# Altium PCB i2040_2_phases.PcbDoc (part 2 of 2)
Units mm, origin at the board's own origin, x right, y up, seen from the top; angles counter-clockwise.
Board outline 90 x 90 mm, 2 copper layers (Top Layer, Bottom Layer), stack 1.575 mm thick; 116 components, 66 nets, 276 pads, 142 vias.
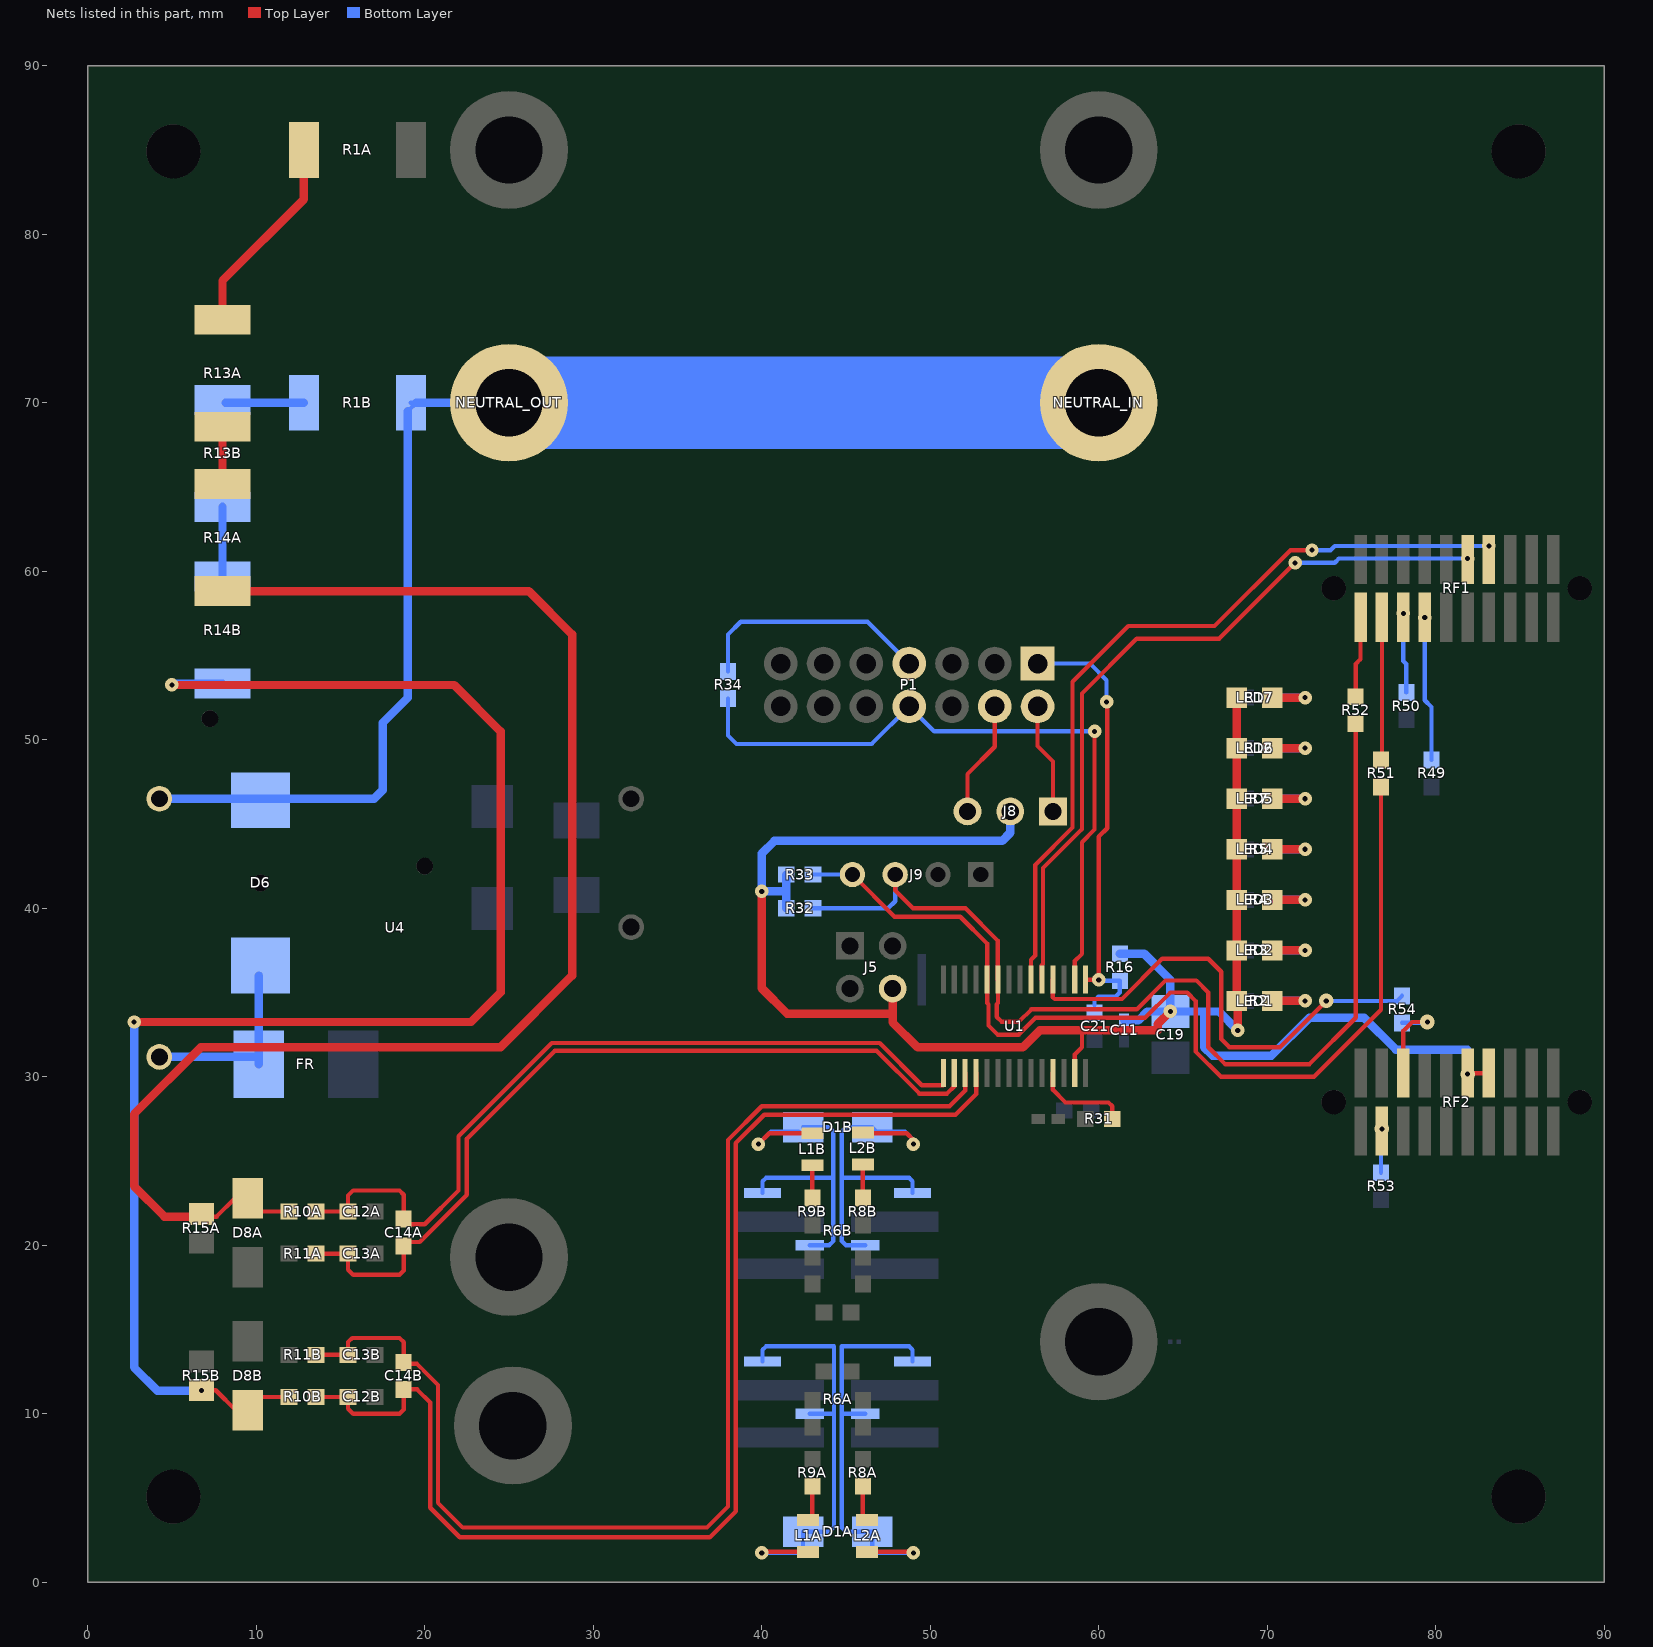
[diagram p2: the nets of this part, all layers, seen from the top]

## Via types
v1: diameter 0.8, hole 0.3, Top Layer to Bottom Layer, 134 vias
v2: diameter 0.864, hole 0.3, Top Layer to Bottom Layer, 6 vias
v3: diameter 0.8, hole 0.3, Top Layer to Bottom Layer, tented top, 2 vias

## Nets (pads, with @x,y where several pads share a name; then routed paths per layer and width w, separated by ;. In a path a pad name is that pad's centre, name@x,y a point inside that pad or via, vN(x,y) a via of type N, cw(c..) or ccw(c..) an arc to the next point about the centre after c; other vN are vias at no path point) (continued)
NetD1A_1: D1A.1 L2A.1 R6A.3 R6A.5 | length 25
  Top Layer w0.254: L2A.1@46.5,1.804 v1@48.946,1.804
  Bottom Layer w0.254: 44.75,10 R6A.3@46.15,10 ; R6A.5@48.95,13.1 48.95,13.8 48.75,14 44.75,14 44.75,3.25 45,3 D1A.1@46.55,3 46.55,2.004 46.804,1.75 v1(49,1.75)
NetD1A_2: D1A.2 L1A.1 R6A.4 R6A.6 | length 25.1
  Top Layer w0.254: v1@40.054,1.804 L1A.1@42.5,1.804
  Bottom Layer w0.254: v1(40,1.75) 42.25,1.75 42.45,1.95 D1A.2@42.45,3 44,3 44.293,3.293 44.293,14 40.25,14 40.05,13.8 R6A.6@40.05,13.1 ; R6A.4@42.85,10 44.25,10
NetD1B_1: D1B.1 L2B.1 R6B.3 R6B.5 | length 20.8
  Top Layer w0.254: L2B.1@46.5,26.646 48.604,26.646 49,26.25 v1(49,26)
  Bottom Layer w0.254: R6B.3@46.15,20 45,20 44.75,20.25 44.75,24 ; R6B.5@48.95,23.1 48.95,23.8 48.75,24 44.75,24 ; v1(49,26) 49,26.25 48.5,26.75 46.8,26.75 D1B.1@46.55,27 45,27 44.75,26.75 44.75,24
NetD1B_2: D1B.2 L1B.1 R6B.4 R6B.6 | length 20.6
  Top Layer w0.254: v1(39.8,26) 40.446,26.646 L1B.1@42.5,26.646
  Bottom Layer w0.254: v1(39.8,26) 40.55,26.75 D1B.2@42.2,26.75 ; R6B.6@40.05,23.1 40.05,23.8 40.25,24 44.25,24 ; D1B.2@42.45,27 44,27 44.25,26.75 44.25,24 ; R6B.4@42.85,20 44,20 44.25,20.25 44.25,24
NetD6_1: D6.1 FR.1 U4.2 | length 11.1
  Bottom Layer w0.254: D6.1@10.15,36 D6.1@10.25,36.1
  Bottom Layer w0.5: U4.2@4.25,31.176 FR.1@10,31.176 ; FR.1@10.15,30.75 D6.1@10.15,36
NetD8A_2: D8A.2 R10A.1 R14A.2 R15A.2 | length 86.9
  Top Layer w0.254: R15A.2@6.5,21.7 7.65,21.7 8.75,22.8 D8A.2@9.5,22.8 ; D8A.2@8.8,22.05 9.5,22.05 9.55,22 R10A.1@11.95,22
  Top Layer w0.5: R15A.2@6.5,21.7 4.55,21.7 2.75,23.5 2.75,27.786 6.714,31.75 24.5,31.75 28.75,36 28.75,56.25 26.175,58.825 R14A.2@8,58.825
NetD8B_2: D8B.2 R10B.1 R14B.2 R15B.2 | length 92.4
  Top Layer w0.254: R15B.2@6.75,11.4 7.6,11.4 8.8,10.2 D8B.2@9.5,10.2 ; D8B.2@9.5,11 R10B.1@11.95,11
  Top Layer w0.5: v1(2.75,33.25) 22.75,33.25 24.5,35 24.5,50.5 21.75,53.25 v1(5,53.25)
  Bottom Layer w0.254: v1(5,53.25) v1@5.075,53.325
  Bottom Layer w0.5: v1(2.75,33.25) 2.75,12.75 4.125,11.375 v1(6.75,11.375) ; v1@5.075,53.325 R14B.2@8,53.325
NetJ8_1: J8.1 P1.2 | length 6.6
  Top Layer w0.254: P1.2@56.37,51.98 56.37,49.63 57.29,48.71 J8.1@57.29,45.75
NetJ8_3: J8.3 P1.4 | length 6.9
  Top Layer w0.254: J8.3@52.21,45.75 52.21,47.96 53.83,49.58 P1.4@53.83,51.98
NetL1A_2: L1A.2 R9A.1 | length 2
  Top Layer w0.254: L1A.2@43,3.704 R9A.1@43,5.7
NetL1B_2: L1B.2 R9B.1 | length 1.9
  Top Layer w0.254: R9B.1@43,22.8 L1B.2@43,24.746
NetL2A_2: L2A.2 R8A.1 | length 2
  Top Layer w0.254: L2A.2@46,3.704 R8A.1@46,5.7
NetL2B_2: L2B.2 R8B.1 | length 1.9
  Top Layer w0.254: R8B.1@46,22.8 L2B.2@46,24.746
NetLED1_2: LED1.2 R2.2 | length 3.9
  Top Layer w0.5: LED1.2@70.3,34.5 v1(72.25,34.5)
  Bottom Layer w0.5: R2.2@70.3,34.5 v1(72.25,34.5)
NetLED2_2: LED2.2 R3.2 | length 3.9
  Top Layer w0.5: LED2.2@70.3,37.5 v1(72.25,37.5)
  Bottom Layer w0.5: R3.2@70.3,37.5 v1(72.25,37.5)
NetLED3_2: LED3.2 R4.2 | length 3.9
  Top Layer w0.5: LED3.2@70.3,40.5 v1(72.25,40.5)
  Bottom Layer w0.5: R4.2@70.3,40.5 v1(72.25,40.5)
NetLED4_2: LED4.2 R5.2 | length 3.9
  Top Layer w0.5: LED4.2@70.3,43.5 v1(72.25,43.5)
  Bottom Layer w0.5: R5.2@70.3,43.5 v1(72.25,43.5)
NetLED5_2: LED5.2 R7.2 | length 3.9
  Top Layer w0.5: LED5.2@70.3,46.5 v1(72.25,46.5)
  Bottom Layer w0.5: R7.2@70.3,46.5 v1(72.25,46.5)
NetLED6_2: LED6.2 R12.2 | length 3.9
  Top Layer w0.5: LED6.2@70.3,49.5 v1(72.25,49.5)
  Bottom Layer w0.5: R12.2@70.3,49.5 v1(72.25,49.5)
NetLED7_2: LED7.2 R17.2 | length 3.9
  Top Layer w0.5: LED7.2@70.3,52.5 v1(72.25,52.5)
  Bottom Layer w0.5: R17.2@70.3,52.5 v1(72.25,52.5)
NetP1_7: P1.7 R34.2 | length 14.3
  Bottom Layer w0.254: R34.2@38,54.05 38,56.25 38.75,57 46.27,57 P1.7@48.75,54.52
NetR1A_2: R1A.2 R13A.1 | length 12.1
  Top Layer w0.5: R13A.1@8,74.925 8,77.25 12.825,82.075 R1A.2@12.825,85
NetR1B_2: R1B.2 R13B.1 | length 4.6
  Bottom Layer w0.5: R13B.1@8.175,70 R1B.2@12.825,70
NetR13A_2: R13A.2 R14A.1 | length 3.4
  Top Layer w0.5: R14A.1@8,65.175 R13A.2@8,68.575
NetR13B_2: R13B.2 R14B.1 | length 4.2
  Bottom Layer w0.5: R14B.1@8,59.675 R13B.2@8,63.825
NetR31_2: R31.2 U1.11 | length 5.7
  Top Layer w0.254: U1.11@57.275,30.225 57.275,29.225 58.025,28.475 60.581,28.475 60.8,28.256 R31.2@60.8,27.5
NetR49_1: R49.1 RF1.14 | length 8.6
  Bottom Layer w0.254: v1(79.345,57.25) 79.345,52.345 79.75,51.94 R49.1@79.75,48.8
NetR50_1: R50.1 RF1.16 | length 4.8
  Bottom Layer w0.254: v1(78.075,57.5) 78.075,54.675 78.25,54.5 R50.1@78.25,52.8
NetR51_1: R51.1 RF1.18 | length 8.4
  Top Layer w0.254: R51.1@76.805,48.855 RF1.18@76.805,57.265
NetR52_1: R52.1 RF1.20 | length 4.6
  Top Layer w0.254: R52.1@75.25,52.8 75.25,54.5 75.535,54.785 RF1.20@75.535,57.265
NetR53_1: R53.1 RF2.18 | length 2.6
  Bottom Layer w0.254: R53.1@76.75,24.3 76.75,26.847 v2(76.805,26.902)
NetR54_2: R54.2 RF2.15 | length 5.7
  Top Layer w0.254: RF2.15@78.075,30.215 78.075,32.725 78.6,33.25 v2(79.5,33.25)
  Bottom Layer w0.254: R54.2@78,33.2 79.45,33.2 v2(79.5,33.25)
NEUTRAL: D6.2 NEUTRAL_IN.1 NEUTRAL_OUT.1 R1B.1 U4.1 | length 83.6
  Bottom Layer w0.254: R1B.1@19,69.5 R1B.1@19.5,70 ; R1B.1@19.175,70 NEUTRAL_OUT.1@25,70
  Bottom Layer w0.5: U4.1@4.25,46.5 17,46.5 17.5,47 17.5,51 19,52.5 R1B.1@19,69.5 ; R1B.1@19.5,70 NEUTRAL_OUT.1@25,70
  Bottom Layer w5.5: NEUTRAL_OUT.1@25,70 NEUTRAL_IN.1@60,70
P1.1: R54.1 U1.18 | length 28.8
  Top Layer w0.254: U1.18@57.275,35.775 57.275,34.725 57.38,34.62 61.38,34.62 63.76,37 66.5,37 67.265,36.235 67.265,32.235 67.75,31.75 70.75,31.75 v2(73.5,34.5)
  Bottom Layer w0.254: v2@73.283,34.5 77.7,34.5 R54.1@78,34.8
RXD: RF1.9 U1.19 | length 44.2
  Top Layer w0.254: U1.19@56.625,35.775 56.625,36.625 56.687,36.687 56.687,42.384 59,44.696 59,52.75 62.25,56 67.155,56 v1(71.655,60.5)
  Bottom Layer w0.254: v1(71.655,60.5) 74,60.5 74.25,60.75 v1(81.885,60.75)
SBWTCK: P1.8 R34.1 U1.16 | length 40.9
  Top Layer w0.254: U1.16@58.575,35.775 58.575,36.867 59,37.292 59,43.919 59.75,44.669 v1(59.75,50.5)
  Bottom Layer w0.254: R34.1@38,52.45 38,50.25 38.5,49.75 46.52,49.75 P1.8@48.75,51.98 50.23,50.5 v1(59.75,50.5)
SBWTDIO: C21.1 P1.1 R16.2 U1.15 | length 27
  Top Layer w0.254: U1.15@59.225,35.775 59.25,35.75 v1(60,35.75) ; v1@60,35.7 60,44.25 60.5,44.75 v1@60.5,52
  Bottom Layer w0.254: P1.1@56.37,54.52 59.48,54.52 60.465,53.535 v1(60.465,52.25) ; C21.1@59.75,34.25 59.75,34.524 59.976,34.75 61,34.75 61.25,35 R16.2@61.25,35.7 v1@60.05,35.7
SIMO: J9.4 R33.1 R51.2 U1.24 | length 60.1
  Top Layer w0.254: J9.4@45.38,42 47.88,39.5 51.783,39.5 53.375,37.908 U1.24@53.375,35.775 53.375,34.383 53.455,34.302 53.455,33.045 54,32.5 55.25,32.5 56.25,33.5 62.75,33.5 64.25,35 65.25,35 65.749,34.501 65.749,31.501 67.25,30 72.777,30 76.75,33.973 R51.2@76.75,47.125
  Bottom Layer w0.254: R33.1@43.05,42 J9.4@45.38,42
SOMI: J9.3 R32.1 R52.2 U1.23 | length 64.4
  Top Layer w0.254: J9.3@47.92,42 47.92,41.06 48.98,40 52.086,40 54,38.086 U1.23@54,35.775 ; U1.23@54.025,35.775 54.025,34.383 53.945,34.302 53.945,33.555 54.23,33.27 55.27,33.27 56,34 62.25,34 63.957,35.707 65.793,35.707 66.5,35 66.5,31.75 67.5,30.75 72.5,30.75 75.25,33.5 R52.2@75.25,50.95
  Bottom Layer w0.254: R32.1@43.05,40 47.5,40 47.92,40.42 J9.3@47.92,42
TXD: RF1.7 U1.20 | length 46.7
  Top Layer w0.254: U1.20@55.975,35.775 55.975,36.942 56.23,37.198 56.23,42.573 58.445,44.788 58.445,53.445 61.75,56.75 66.872,56.75 71.372,61.25 v1(72.655,61.25)
  Bottom Layer w0.254: v1(72.655,61.25) 73.75,61.25 74,61.5 v1(83.155,61.5)
VCC: C11.1 C19.1 J5.4 J8.2 LED1.1 LED2.1 LED3.1 LED4.1 LED5.1 LED6.1 LED7.1 R16.1 R32.2 R33.2 RF2.7 RF2.9 U1.13 | length 114.4
  Top Layer w0.254: U1.13@58.575,30.225 58.575,31.325 59,31.75 59,32.75 ; LED1.1@68.195,34.495 LED1.1@68.25,34.441 ; RF2.9@81.885,30.215 RF2.7@83.155,30.215
  Top Layer w0.5: v1(40,41) 40,35.25 41.5,33.75 47.77,33.75 ; J5.4@47.77,35.23 47.77,33.75 ; v1(64.25,33.875) 63.5,33.125 63.5,32.75 56.5,32.75 55.5,31.75 49.25,31.75 47.77,33.23 47.77,33.75 ; LED1.1@68.195,34.495 LED2.1@68.195,37.495 LED3.1@68.195,40.495 LED4.1@68.195,43.495 LED5.1@68.195,46.495 LED6.1@68.195,49.495 LED7.1@68.195,52.495 ; v1(68.25,32.75) LED1.1@68.25,34.441
  Bottom Layer w0.5: R32.2@41.45,40 41.45,41 ; R33.2@41.45,42 41.45,41 ; J8.2@54.75,45.75 54.75,44.48 54.27,44 40.75,44 40,43.25 v1(40,41) 41.45,41 ; R16.1@61.25,37.3 62.7,37.3 64.25,35.75 v1(64.25,33.875) ; C11.1@61.5,33.35 62.35,33.35 62.875,33.875 v1(64.25,33.875) ; 66.25,33.875 66.25,31.75 66.75,31.25 70.25,31.25 72.5,33.5 75.75,33.5 77.635,31.615 81.885,31.615 v2(81.885,30.152) ; v1(68.25,32.75) 67.125,33.875 v1(64.25,33.875)
VIN_MA: C13A.2 C14A.2 R11A.2 U1.2 | length 48.8
  Top Layer w0.254: R11A.2@13.55,19.5 C13A.2@15.45,19.5 15.45,18.55 15.75,18.25 18.5,18.25 18.75,18.5 C14A.2@18.75,19.525 ; C14A.2@18.75,20.2 19.7,20.2 22.5,23 22.5,26.321 27.722,31.543 46.811,31.543 49.353,29 51,29 51.425,29.425 U1.2@51.425,30.225
VIN_MB: C12B.1 C14B.1 R10B.2 U1.4 | length 73.5
  Top Layer w0.254: R10B.2@13.55,11 C12B.1@15.45,11 15.45,10.3 15.75,10 18.5,10 18.75,10.25 C14B.1@18.75,11.45 19.55,11.45 20.33,10.67 20.33,4.42 22.08,2.67 36.92,2.67 38.457,4.207 38.457,26.061 40.147,27.75 51.5,27.75 52.725,28.975 U1.4@52.725,30.225
VIN_PA: C12A.1 C14A.1 R10A.2 U1.1 | length 48
  Top Layer w0.254: R10A.2@13.55,22 C12A.1@15.45,22 15.45,22.95 15.75,23.25 18.5,23.25 18.75,23 C14A.1@18.75,21.55 19.05,21.25 20,21.25 22,23.25 22,26.467 27.533,32 47,32 49.5,29.5 U1.1@50.775,29.5 ; U1.1@50.775,29.552 U1.1@50.775,30.225
VIN_PB: C13B.2 C14B.2 R11B.2 U1.3 | length 73.3
  Top Layer w0.254: R11B.2@13.55,13.5 C13B.2@15.45,13.5 15.45,14.254 15.696,14.5 18.5,14.5 18.75,14.25 C14B.2@18.75,13.05 ; C14B.2@18.75,12.963 19.537,12.963 20.787,11.713 20.787,4.713 22.25,3.25 36.75,3.25 38,4.5 38,26.25 40,28.25 51.137,28.25 52.075,29.188 U1.3@52.075,30.225
pads on no net: H1.1 H2.1 H3.1 H4.1 Logo1.0 P1.3 P1.5 P1.6 P1.10 P1.11 P1.12 P1.13 P1.14 RF1. RF1.2 RF1.4 RF1.5 RF1.6 RF1.8 RF1.10 RF1.11 RF1.12 RF1.13 RF1.15 RF1.17 RF2. RF2.1 RF2.3 RF2.4 RF2.5 RF2.6 RF2.8 RF2.10 RF2.11 RF2.12 RF2.13 RF2.14 RF2.16 RF2.17 RF2.19

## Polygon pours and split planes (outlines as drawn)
AGND on Bottom Layer "Bottom Layer-No Net" (solid, remove dead copper, pour order 4): 1,32.5 65.75,32.5 65.75,1 1,1 1,35.75
DGND on Bottom Layer "Bottom Layer-No Net 1" (solid, pour order 7): 72.5,55 72.5,65 89,65 89,1 66.25,1 66.25,55 72.5,55
DGND on Bottom Layer "Bottom Layer-No Net 2" (solid, pour order 13): 35,57.5 65,57.5 65,34.35 64.9,34.25 35,34.25
AGND on Top Layer "Top Layer-No Net" (solid, remove dead copper, pour order 6): 1,1 1,33.25 65.75,33.25 65.75,1 1,1
DGND on Top Layer "Top Layer-No Net 1" (solid, pour order 9): 72.5,65 89,65 89,1 66.25,1 66.25,55 72.5,55 72.5,65
DGND on Top Layer "Top Layer-No Net 2" (solid, pour order 11): 35,57.5 65,57.5 65,34.25 35,34.25

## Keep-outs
Keep-Out Layer:
  lines w1.2: -0.6,0 ccw(c0,0) 0,-0.6 90,-0.6 ccw(c90,0) 90.6,0 90.6,90 ccw(c90,90) 90,90.6 0,90.6 ccw(c0,90) -0.6,90 -0.6,0
  text ".Layer_Name" at 14.656,-21.806 h1.52

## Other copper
Top Layer:
  text ".Layer_Name" at 14.656,-21.806 h1.52
Bottom Layer:
  rectangle net LIVE_1B: 35,16.6 38.5,22
  rectangle net LIVE_1_A: 35,6.6 38.5,12
  rectangle net LIVE_1: 50.5,16.6 54,22
  rectangle net LIVE_1: 50.5,6.6 54,12
  text ".Layer_Name" at 14.656,-21.806 h1.52

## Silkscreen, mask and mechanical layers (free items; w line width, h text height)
Top Overlay:
  text "Danger High Voltage" at 28.5,76.75 h1.5
  text "CAUTION" at 13,62 h2
  text "MSP430i2040 2 Phases Embedded Meter EVM" at 36,61.75 h1.8
  text "Debugging Interfaces" at 13,59.75 h2
  text ".PCB_Rev" at 36,59 h1.52
  text "ARE NOT ISOLATED" at 13,57.5 h2
  text "Disconnect Debugger" at 13,55.5 h2
  text "Before Applying Line" at 13,53.25 h2
  text "Voltage to the Board" at 13,51 h2
  text "EXT 2-3" at 50.5,47.5 h0.8
  text "FET 1-2" at 54.75,43.25 h0.8
  text "0V" at 41.75,37.25 h1.02
  text "3.3V" at 40,34.5 h1.02
  text "CAUTION" at 80,34.25 h2 r90
  text "Serial Interfaces" at 82.9,34.2 h2 r90
  text "ARE NOT ISOLATED" at 84.9,34.2 h2 r90
  text "Danger High Voltage" at 56,9 h1.5
  text "Danger High Voltage" at 10.5,2.5 h1.5
  text ".Layer_Name" at 14.656,-21.806 h1.52
Bottom Overlay:
  rectangle: 30.38,92 38,94.54
  text ".PRJ_Number" at 54.916,92.254 h1.52
  text "-" at 39.651,91.987 h1.52
  text "Danger High Voltage" at 55.75,76.75 h1.5
  text "Texas Instruments" at 49.5,61.5 h1.52
  text ".CopyrightYear" at 58.25,61.5 h1.52
  text "©" at 61,61.5 h2.67
  text "Caution Hot Surface" at 54.5,14.25 h1.5
  text "Danger High Voltage" at 83.192,9.148 h1.5
  text "Danger High Voltage" at 37.192,2.398 h1.5
  text "UL94V-0" at 79.75,1.25 h1.52
  text ".Layer_Name" at 14.656,-21.806 h1.52
Top Paste:
  text ".Layer_Name" at 14.656,-21.806 h1.52
Bottom Paste:
  text ".Layer_Name" at 14.656,-21.806 h1.52
Top Solder:
  text ".Layer_Name" at 14.656,-21.806 h1.52
  text ".Layer_Name" at 14.656,-21.806 h1.52
Bottom Solder:
  text ".Layer_Name" at 14.656,-21.806 h1.52
Drill Guide:
  text ".Layer_Name" at 14.656,-21.806 h1.52
M1 Board Outline:
  the board outline again, w0.254
  text ".PRJ_Title" at 81.5,-5 h1.02
M2 Board Dimensions:
  rectangle: 3.162,-10.427 12.687,-7.252
  rectangle: -0.013,-7.252 3.162,-4.077
  lines w0.178: -0.013,-7.252 25.387,-7.252 ; 3.162,-10.427 3.162,-4.077 ; 6.337,-10.427 6.337,-4.077 ; 12.687,-10.427 12.687,-4.077 ; 19.037,-10.427 19.037,-4.077 ; -0.013,-10.427 -0.013,-4.077 25.387,-4.077 25.387,-10.427 -0.013,-10.427
  lines w0.254: -0.013,-12.078 -0.013,-11.57 ; 1.511,-12.332 -0.013,-11.824 ; 1.511,-11.316 -0.013,-11.824 ; 6.187,-11.824 -0.013,-11.824 ; 19.188,-11.824 25.387,-11.824 ; 23.863,-12.332 25.387,-11.824 ; 23.863,-11.316 25.387,-11.824 ; 25.387,-12.078 25.387,-11.57
  text ".PRJ_Title" at 81.5,-5 h1.02
  text "25.4 (mm)" at 6.441,-12.738 h1.52
M3 3D STEP Top:
  text ".Layer_Name" at 14.656,-21.806 h1.52
M4 3D STEP Bottom:
  text ".Layer_Name" at 14.656,-21.806 h1.52
M5 Assembly Top:
  lines w0.254: -7.417,-23.626 160.223,-23.626 ; -7.417,-18.462 160.274,-18.462 ; -7.417,-13.297 -7.417,-28.791 94.31,-28.791 160.274,-28.791 160.274,-13.297 -7.404,-13.297 -7.404,-28.791 32.614,-28.791 ; 55.194,-28.791 55.194,-13.297 ; 87.376,-18.462 87.376,-13.297 ; 108.712,-18.462 108.712,-13.297 ; 124.511,-28.956 124.511,-23.804
  text "COMPONENTS MARKED 'DNP' SHOULD NOT BE POPULATED." at 29.299,-8.09 h1.52
  text "ASSEMBLY VARIANT:" at 29.286,-11.024 h1.52
  text ".VariantName" at 55.601,-11.024 h1.52
  text "PCB VIEWED FROM TOP SIDE" at -5.804,-16.654 h1.52
  text "BOARD #:" at 57.099,-16.654 h1.52
  text ".PRJ_Number" at 70.955,-16.654 h1.52
  text "REV:" at 92.405,-16.654 h1.52
  text ".PCB_Rev" at 99.809,-16.654 h1.52
  text "SVN REV:" at 113.69,-16.654 h1.52
  text ".VersionControl_RevNumber" at 126.543,-16.654 h1.52
  text "IGNORE ->" at -5.804,-21.806 h1.52
  text "PLOT NAME =" at -5.804,-27.034 h1.52
  text ".plot_File_Name" at 14.656,-27.034 h1.52
  text "GENERATED    :" at 57.15,-27.034 h1.52
  text ".Print_Date" at 79.235,-27.034 h1.52
  text ".Print_Time" at 97.752,-27.034 h1.52
  text "TEXAS INSTRUMENTS" at 129.87,-27.034 h1.52
M6 Assembly Bottom:
  lines w0.254: -7.429,-18.474 160.261,-18.474 ; -7.379,-23.639 160.261,-23.639 ; 28.334,-28.969 28.334,-23.817 ; 44.133,-18.474 44.133,-13.31 ; 65.468,-18.474 65.468,-13.31 ; 97.65,-28.804 97.65,-13.31 ; 120.231,-28.804 160.249,-28.804 160.249,-13.31 -7.429,-13.31 -7.429,-28.804 58.534,-28.804 160.261,-28.804 160.261,-13.31
  text "COMPONENTS MARKED 'DNP' SHOULD NOT BE POPULATED." at 154.991,-8.077 h1.52
  text ".VariantName" at 128.473,-11.024 h1.52
  text "ASSEMBLY VARIANT:" at 154.864,-11.024 h1.52
  text ".VersionControl_RevNumber" at 26.302,-16.667 h1.52
  text "SVN REV:" at 39.154,-16.667 h1.52
  text ".PCB_Rev" at 53.035,-16.667 h1.52
  text "REV:" at 60.439,-16.667 h1.52
  text ".PRJ_Number" at 81.89,-16.667 h1.52
  text "BOARD #:" at 95.745,-16.667 h1.52
  text "PCB VIEWED FROM BOTTOM SIDE" at 158.648,-16.667 h1.52
  text "IGNORE ->" at 64.715,-21.806 h1.52
  text "TEXAS INSTRUMENTS" at 22.974,-27.047 h1.52
  text ".Print_Time" at 55.093,-27.047 h1.52
  text ".Print_Date" at 73.609,-27.047 h1.52
  text "GENERATED    :" at 95.694,-27.047 h1.52
  text ".plot_File_Name" at 138.189,-27.047 h1.52
  text "PLOT NAME =" at 158.648,-27.047 h1.52
M9 Title Sheet:
  drawing of 57 lines, arcs and shapes, not listed
  text "1" at 18.792,204.127 h1.78
  text "2" at 82.182,204.127 h1.78
  text "3" at 145.411,204.127 h1.78
  text "4" at 209.08,204.127 h1.78
  text "5" at 272.555,204.127 h1.78
  text "6" at 336.182,204.127 h1.78
  text "A" at -10.579,175.095 h1.78
  text "A" at 365.341,175.095 h1.78
  text "B" at -10.579,114.643 h1.78
  text "B" at 365.341,114.643 h1.78
  text "C" at -10.579,54.318 h1.78
  text "C" at 365.341,54.318 h1.78
  text "PROJECT TITLE:" at 288.125,7.048 h1.14
  text ".PRJ_Title" at 289.395,3.662 h1.78
  text "DESIGNED FOR:" at 288.125,-0.597 h1.14
  text ".PRJ_Customer" at 289.395,-4.153 h1.78
  text "D" at -10.579,-5.88 h1.78
  text "D" at 365.341,-5.88 h1.78
  text "FILE NAME:" at 288.125,-8.217 h1.14
  text ".PCB_File_Name_No_Path" at 289.395,-11.265 h1.78
  text "Texas Instruments (TI) and/or its licensors do not warrant the accuracy or completeness of this specification" at 161.9,-15.376 h1.14
  text "ENGINEER:" at 288.125,-15.583 h1.14
  text "LAYOUT BY:" at 326.352,-15.583 h1.14
  text "or any information contained therein. TI and/or its licensors do not warrant that this design will meet" at 160.757,-18.237 h1.14
  text ".PRJ_Engineer" at 289.395,-19.52 h1.78
  text ".PCB_Layout" at 327.635,-19.52 h1.78
  text "the specifications, will be suitable for your application or fit for any particular purpose, or will operate in" at 160.757,-21.099 h1.14
  text ".Layer_Name" at 14.656,-21.806 h1.52
  text "ALTIUM DESIGNER VERSION:" at 326.352,-23.457 h1.14
  text "an implementation. TI and/or its licensors do not warrant that the design is production worthy. You should" at 160.757,-23.961 h1.14
  text "completely validate and test your design implementation to confirm the system functionality for your application." at 161.9,-26.822 h1.14
  text ".print_Scale" at 289.395,-26.843 h1.78
  text ".Application_BuildNumber" at 327.635,-26.843 h1.78
  text "1" at 18.792,-32.093 h1.78
  text "2" at 82.182,-32.093 h1.78
  text "3" at 145.411,-32.093 h1.78
  text "4" at 209.08,-32.093 h1.78
  text "5" at 272.555,-32.093 h1.78
  text "6" at 336.182,-32.093 h1.78
M10 Fab Notes:
  drawing of 212 lines, arcs and shapes, not listed
  text "DESIGN INFORMATION" at 314.478,172.974 h1.52
  text "(REFER ALSO ARRAY/PANEL PROFILING INFORMATION)" at 305.294,168.866 h1.52
  text "BOARD SIZE" at 287.87,168.758 h1.52
  text "3450MIL" at 299.613,165.511 h1.52
  text "X" at 312.457,165.511 h1.52
  text "4950MIL" at 318.333,165.511 h1.52
  text "Number of Layers :" at 298.106,160.503 h1.52
  text "2" at 325.914,160.249 h1.52
  text "MIN. TRACK WIDTH:" at 298.106,156.972 h1.52
  text "8" at 325.951,156.972 h1.52
  text "MIL" at 329.881,156.972 h1.52
  text "MIN. CLEARANCE:" at 298.106,153.619 h1.52
  text "8" at 325.951,153.619 h1.52
  text "MIL" at 329.881,153.619 h1.52
  text "MIN. VIA PAD SIZE:" at 298.106,150.266 h1.52
  text "24" at 325.189,150.266 h1.52
  text "MIL" at 329.881,150.266 h1.52
  text "0.05mm (2MIL)" at 315.759,146.667 h1.52
  text "MINIMUM ANNULAR RING" at 289.744,146.558 h1.52
  text "EXTERNAL" at 333.742,146.558 h1.52
  text "PER" at 294.824,143.561 h1.52
  text "IPC-D-275 CLASS 2 LEVEL C" at 300.412,143.561 h1.52
  text "MIL, HOLES" at 338.213,140.709 h1.52
  text "+/-" at 328.244,140.691 h1.52
  text "+/-" at 349.936,140.691 h1.52
  text "REGISTRATION TOLERANCES:" at 289.744,140.564 h1.52
  text "METAL" at 320.218,140.564 h1.52
  text "5" at 334.853,140.564 h1.52
  text "3" at 356.012,140.564 h1.52
  text "MIL" at 358.964,140.564 h1.52
  text "MATERIAL:" at 287.844,135.243 h1.52
  text "FR-4 High Tg" at 312.9,131.679 h1.52
  text "FR-408" at 298.538,131.461 h1.52
  text "X" at 309.003,131.461 h1.52
  text "OTHER" at 336.333,131.461 h1.52
  text "62 MIL (1.6mm) +/-10%" at 306.668,127.328 h1.52
  text "THICKNESS:" at 289.744,127.219 h1.52
  text "X" at 303.413,127.219 h1.52
  text "OTHER" at 339.305,127.219 h1.52
  text "TOLERANCE:" at 289.744,123.206 h1.52
  text "X" at 311.062,123.206 h1.52
  text "ANSI IPC-6012 TYPE 3 CLASS 2" at 315.81,123.206 h1.52
  text "OTHER +/-" at 315.81,119.244 h1.52
  text "BOW & TWIST:" at 289.744,115.256 h1.52
  text "X" at 311.062,115.256 h1.52
  text "ANSI IPC-6012 TYPE 3 CLASS 2" at 315.81,115.256 h1.52
  text "OTHER +/-" at 315.81,111.23 h1.52
  text "COPPER THICKNESS (FINISHED):" at 287.844,107.788 h1.52
  text "1.4MIL (1oz)" at 310.196,103.909 h1.52
  text "2MIL (1.4oz)" at 329.678,103.909 h1.52
  text "2.8MIL (2oz)" at 348.144,103.909 h1.52
  text "OUTER:" at 296.912,103.801 h1.52
  text "X" at 306.934,103.784 h1.52
  text "1.4MIL (1oz)" at 310.196,99.922 h1.52
  text "2.8MIL (2oz)" at 329.678,99.922 h1.52
  text "N/A" at 348.132,99.931 h1.52
  text "INNER SIGNAL:" at 289.57,99.813 h1.52
  text "X" at 306.97,99.813 h1.52
  text "DRILLING:" at 287.844,96.282 h1.52
  text "REFERENCE:" at 289.744,93.31 h1.52
  text "X" at 306.209,93.31 h1.52
  text "AS SHOWN" at 310.958,93.31 h1.52
  text "X" at 329.094,93.31 h1.52
  text "NC_DRILL FILES" at 332.574,93.31 h1.52
  text "PTH MIN COPPER THICKNESS:" at 289.744,89.297 h1.52
  text "X" at 324.039,89.297 h1.52
  text "1MIL" at 327.519,89.297 h1.52
  text "OTHER" at 340.143,89.297 h1.52
  text "BOARD FINISH:" at 287.844,85.259 h1.52
  text "SILKSCREEN:" at 291.787,82.261 h1.52
  text "X" at 315.886,82.261 h1.52
  text "TOP" at 319.086,82.261 h1.52
  text "X" at 328.84,82.261 h1.52
  text "BOTTOM" at 332.066,82.261 h1.52
  text "SILKSCREEN COLOR:" at 291.787,78.02 h1.52
  text "X" at 315.86,78.02 h1.52
  text "WHITE" at 319.086,78.02 h1.52
  text "OTHER" at 332.066,78.02 h1.52
  text "SOLDER RESIST COLOR:" at 291.787,73.702 h1.52
  text "X" at 306.208,69.658 h1.52
  text "GREEN" at 309.434,69.658 h1.52
  text "BLUE" at 324.446,69.658 h1.52
  text "OTHER" at 338.111,69.658 h1.52
  text "IMMERSION GOLD (ENIG)" at 314.794,64.87 h1.52
  text "ENEPIG" at 348.767,64.786 h1.52
  text "SURFACE FINISH:" at 287.844,64.761 h1.52
  text "X" at 310.045,64.761 h1.52
  text "IMM. TIN/SILVER OR EQUIV" at 296.215,60.773 h1.52
  text "OTHER" at 332.574,60.773 h1.52
  text "ARRAY/PANEL:" at 287.844,56.226 h1.52
  text "CUT AND TRIM PER MECH LAYER 1" at 314.794,56.118 h1.52
  text "N.C. ROUTE" at 314.794,52.264 h1.52
  text "X" at 332.04,52.264 h1.52
  text "V. SCORE" at 336.79,52.264 h1.52
  text "CERTIFICATION:" at 287.844,48.784 h1.52
  text "MATERIALS AND WORKMANSHIP FOR ALL PCBS" at 306.259,48.784 h1.52
  text "TO MEET OR EXCEED THE REQUIREMENTS OF:" at 306.259,46.295 h1.52
  text "X" at 296.773,42.828 h1.52
  text "ANSI IPC-A-600F CLASS ->" at 300.303,42.828 h1.52
  text "X" at 341.935,42.828 h1.52
  text "2" at 344.956,42.828 h1.52
  text "1" at 336.955,42.79 h1.52
  text "3" at 353.948,42.79 h1.52
  text "X" at 296.825,38.777 h1.52
  text "UL 94V-0" at 300.303,38.777 h1.52
  text "X" at 317.45,38.777 h1.52
  text "RoHS" at 320.928,38.777 h1.52
  text "OTHER" at 337.296,38.777 h1.52
  text "PER ORDER" at 347.381,38.777 h1.52
  text "ADDITIONAL REQUIREMENTS:" at 287.844,35.195 h1.52
  text "MICROSECTION:" at 289.744,32.274 h1.52
  text "YES" at 312.749,32.274 h1.52
  text "REQUIRED" at 334.631,28.308 h1.52
  text "BARE BOARD ELEC. TEST:" at 289.744,28.236 h1.52
  text "NONE" at 322.909,28.236 h1.52
  text "X" at 331.405,28.236 h1.52
  text "PER ORDER" at 349.668,28.236 h1.52
  text "MANUFACTURER'S UL:" at 289.744,24.248 h1.52
  text "RAIL" at 319.353,24.139 h1.52
  text "METAL" at 331.845,24.139 h1.52
  text "X" at 341.376,24.13 h1.52
  text "SILK" at 344.842,24.139 h1.52
  text ".Layer_Name" at 14.656,-21.806 h1.52
M11 Gerber Information:
  lines w0.254: -7.417,-23.626 160.223,-23.626 ; -7.417,-18.462 160.274,-18.462 ; -7.417,-13.297 -7.417,-28.791 94.31,-28.791 160.274,-28.791 160.274,-13.297 -7.404,-13.297 -7.404,-28.791 32.614,-28.791 ; 55.194,-28.791 55.194,-13.297 ; 87.376,-18.462 87.376,-13.297 ; 108.712,-18.462 108.712,-13.297 ; 124.511,-28.956 124.511,-23.804
  text "ALL ARTWORK VIEWED FROM TOP SIDE" at -5.804,-16.654 h1.52
  text "BOARD #:" at 57.099,-16.654 h1.52
  text ".PRJ_Number" at 70.955,-16.654 h1.52
  text "REV:" at 92.405,-16.654 h1.52
  text ".PCB_Rev" at 99.809,-16.654 h1.52
  text "SVN REV:" at 113.69,-16.654 h1.52
  text ".VersionControl_RevNumber" at 126.543,-16.654 h1.52
  text "LAYER NAME =" at -5.804,-21.806 h1.52
  text "PLOT NAME =" at -5.804,-27.034 h1.52
  text ".plot_File_Name" at 14.656,-27.034 h1.52
  text "GENERATED    :" at 57.15,-27.034 h1.52
  text ".Print_Date" at 79.235,-27.034 h1.52
  text ".Print_Time" at 97.752,-27.034 h1.52
  text "TEXAS INSTRUMENTS" at 129.87,-27.034 h1.52
M12 Stackup:
  lines w0.152: 288.544,189.484 353.314,189.484 ; 288.544,192.136 353.314,192.136 ; 287.02,177.165 ccw(c287.884,177.165) 287.884,176.301 353.974,176.301 ccw(c353.974,177.165) 354.838,177.165 354.838,195.097 ccw(c353.974,195.097) 353.974,195.961 287.884,195.961 ccw(c287.884,195.097) 287.02,195.097 287.02,177.165
  text "The Stackup Legend below this is static." at 294.78,200.012 h1.52
  text "If you change the stackup, update the Legend." at 295.034,197.726 h1.52
  text "Layer Stack Up Detail for: Ref_Design.PcbDoc" at 288.544,192.966 h1.45
  text "Layer" at 288.544,191.145 h0.61
  text "Gerber" at 311.298,191.145 h0.61
  text "Copper" at 325.611,191.145 h0.61
  text "Dielectric" at 340.92,191.145 h0.61
  text "Name" at 288.544,189.926 h0.61
  text "Document" at 311.298,189.926 h0.61
  text "Thickness" at 325.611,189.926 h0.61
  text "Material" at 340.92,189.926 h0.61
  text "Top Solder Mask" at 288.544,187.565 h0.86
  text "(.GTS)" at 311.298,187.565 h0.86
  text "Solder Resist" at 340.92,187.565 h0.86
  text "Top Layer" at 288.544,185.107 h0.86
  text "(.GTL)" at 311.298,185.107 h0.86
  text "1.4mil" at 325.611,185.107 h0.86
  text "FR-4" at 340.92,183.879 h0.86
  text "Bottom Layer" at 288.544,182.65 h0.86
  text "(.GBL)" at 311.298,182.65 h0.86
  text "1.4mil" at 325.611,182.65 h0.86
  text "Bottom Solder Mask" at 288.544,180.192 h0.86
  text "(.GBS)" at 311.298,180.192 h0.86
  text "Solder Resist" at 340.92,180.192 h0.86
  text ".Layer_Name" at 14.656,-21.806 h1.52
M13 Component Bodies Top:
  text ".Layer_Name" at 14.656,-21.806 h1.52
M14 Component Bodies Bottom:
  text ".Layer_Name" at 14.656,-21.806 h1.52
M15 Courtyards Top:
  text ".Layer_Name" at 14.656,-21.806 h1.52
M16 Courtyards Bottom:
  text ".Layer_Name" at 14.656,-21.806 h1.52
Drill Drawing:
  text ".legend" at 130.112,18.428 h1.52
  text "Drill Table" at 129.794,13.97 h1.52
  text ".Layer_Name" at 14.656,-21.806 h1.52

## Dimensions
0,0 to 90,0 on M2 Board Dimensions
0,0 to 0,90 on M2 Board Dimensions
